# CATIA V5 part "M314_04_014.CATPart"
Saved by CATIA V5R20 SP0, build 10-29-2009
Part number: M314_04_014
Source: Unknown
Property "ARTICLENO": "M314-04-014"
Property "B": "35.000"
Property "BOMINFO": "M314-04-014"
Property "CODE": "M314-04-014"
Property "D": "8.000"
Property "FINALFORCE": "98.0 (10)"
Property "INITIALFORCE": "29.4 (3)"
Property "K": "50.000"
Property "L": "155.000"
Property "LINA": "M314-04-014"
Property "M": "M16x2.0"
Property "NB": "M314-04-014"
Property "NBSYN": "$CODE."
Property "NN": "M314-04"
Property "NT": "Spring Plunger"
Property "SUPPLIER": "CF"
Property "SW": "8.000"
Bounding box of the stored display mesh (mm): x -8 to 8, y 0 to 205, z -8 to 8
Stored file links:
  C:\Users\Utente\Desktop\3D files M314\M314_04_014.CATPart
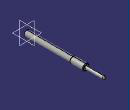
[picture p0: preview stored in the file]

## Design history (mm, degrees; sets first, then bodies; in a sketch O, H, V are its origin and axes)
Body1 "Geometry.1" (main body)
  Solid1 "M314_04_014.catpart": solid without history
